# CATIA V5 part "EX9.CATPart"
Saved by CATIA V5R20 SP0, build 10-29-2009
Part number: EX9
Bounding box of the stored display mesh (mm): x -85 to 62, y -44.578 to 148.939, z 0 to 10
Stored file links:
  E:\Nouveau dossier\tarek\mécaniquee\Catia\TP 0\EX9.CATPart
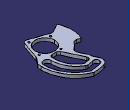
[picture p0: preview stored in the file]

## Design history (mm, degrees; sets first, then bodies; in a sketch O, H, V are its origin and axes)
Set1
  DatumSurface1 to DatumSurface54
Body1 (main body)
